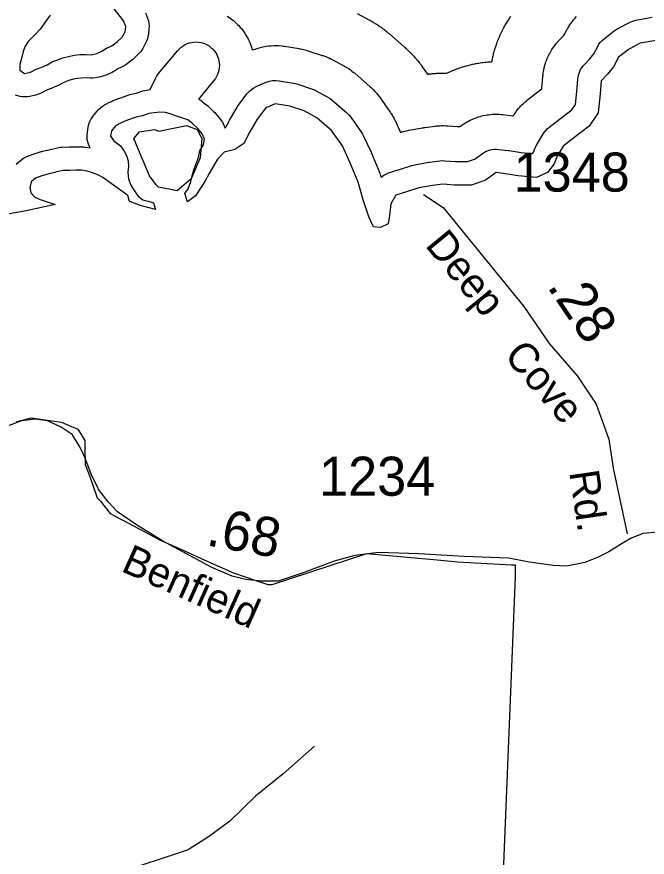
# Model space of a CAD drawing. Extents: x 1113032 to 1302912, y 664689 to 832535.
# Drawn here: x 1144794 to 1146811, y 736082 to 738772 of the extents above; entities that cross this region are included whole.
import ezdxf

# ---------------------------------------------------------------- set-up
doc = ezdxf.new("R2010")
doc.units = 0
for name, color, linetype in [('Exist Boundary Land Use Park State Division NC Parks and Recreation', 7, 'Continuous'), ('Exist Hydrographic Buffer Line', 7, 'Continuous'), ('Exist Hydrographic Island Shore', 7, 'Continuous'), ('Exist Hydrographic Lake Shore', 7, 'Continuous'), ('Exist Hydrographic Misc Water Feature', 7, 'Continuous'), ('Exist Road Non-System Type 51', 7, 'Continuous'), ('Exist Road Non-System Type 51 Label', 7, 'Continuous'), ('Exist Road Secondary Mileage Hundredths English Label', 7, 'Continuous'), ('Exist Road Secondary Type 51 Attributed', 7, 'Continuous'), ('Exist Road Secondary Type 51 Label', 7, 'Continuous'), ('Exist Road Secondary Type 51 Number Label', 7, 'Continuous')]:
    doc.layers.add(name, color=color, linetype=linetype)

msp = doc.modelspace()

# ---------------------------------------------------------------- linework, layer by layer
at = {"layer": 'Exist Boundary Land Use Park State Division NC Parks and Recreation'}
msp.add_lwpolyline([(1144791.7, 737475.3), (1144840.3, 737487.9), (1144869.2, 737483.6), (1144936.9, 737474.7), (1144954.2, 737467.5), (1144988.8, 737451.7), (1145011.3, 737415.5), (1145011.3, 737391.4), (1145012.9, 737338.9), (1145024, 737309.1), (1145038.6, 737269.2), (1145051.2, 737232.5), (1145060.1, 737222.6), (1145092.1, 737182.2), (1145108.3, 737173.3), (1145203.3, 737124), (1145249.9, 737098.3), (1145318.6, 737067.9), (1145395.6, 737032.5), (1145487.2, 736992.7), (1145562.1, 736966.9), (1145597.3, 736955.2), (1145611.3, 736955.2), (1145913.9, 737053.7), (1146150.7, 737032.5), (1146205, 737028), (1146279.5, 737023.3), (1146376.5, 737018.2), (1146388.2, 737017.7), (1146388.6, 736979.2), (1146300.2, 734800.2)], dxfattribs=at)
at = {"layer": 'Exist Hydrographic Buffer Line'}
for points in [[(1145206, 738784.8), (1145212.5, 738767.4), (1145215, 738759.1), (1145216.6, 738750.5), (1145217.2, 738741.8), (1145216.7, 738733.2), (1145214.8, 738715.2), (1145213.6, 738707.9), (1145211.8, 738700.9), (1145209.3, 738694), (1145206.1, 738687.4), (1145197, 738670.6), (1145190.5, 738660.7), (1145182.6, 738651.9), (1145168, 738638.2), (1145164.9, 738635.4), (1145161.5, 738632.7), (1145142.5, 738618.4), (1145135.1, 738613.6), (1145127.1, 738609.6), (1145116.7, 738605.1), (1145107, 738598.7), (1145102.9, 738596.3), (1145098.6, 738594), (1145082.3, 738586.2), (1145072.8, 738582.4), (1145062.9, 738579.9), (1145044.5, 738576.7), (1145036.5, 738575.7), (1145028.6, 738575.6), (1145013.2, 738576.1), (1145000.4, 738575.7), (1144988, 738574.3), (1144975.6, 738572), (1144963.4, 738568.7), (1144951.5, 738564.6), (1144940.1, 738559.6), (1144926.1, 738552.2), (1144923.4, 738550.8), (1144920.7, 738549.6), (1144903.6, 738542.2), (1144902.2, 738541.6), (1144900.7, 738541), (1144886.3, 738535.4), (1144871.6, 738527.8), (1144862.8, 738524), (1144853.6, 738521.3), (1144835.3, 738517.2), (1144827.7, 738515.9), (1144819.9, 738515.4), (1144812.1, 738515.7), (1144804.4, 738516.8), (1144796.8, 738518.7), (1144789.5, 738521.4)], [(1144791.5, 738300.3), (1144805.4, 738312), (1144815.3, 738319.1), (1144826.2, 738324.5), (1144846.1, 738332.4), (1144849.1, 738333.5), (1144852.2, 738334.5), (1144871.7, 738340.4), (1144874, 738341), (1144876.4, 738341.6), (1144906, 738348.5), (1144906.2, 738348.5), (1144906.3, 738348.5), (1144925, 738352.8), (1144932.1, 738354), (1144939.2, 738354.6), (1144960.9, 738355.3), (1144979.5, 738356), (1144982.4, 738356.1), (1144985.3, 738356.1), (1145003.5, 738355.4), (1145007.9, 738355.1), (1145012.2, 738354.6), (1145028.8, 738352), (1145026.1, 738357), (1145023.2, 738364), (1145021, 738371.3), (1145019.5, 738378.7), (1145018.8, 738386.2), (1145018.9, 738393.8), (1145019.7, 738401.3), (1145022.6, 738419), (1145024.7, 738428.2), (1145027.9, 738436.9), (1145032.1, 738445.3), (1145037.4, 738453), (1145049.9, 738469.1), (1145055.2, 738475.3), (1145061.2, 738480.8), (1145067.7, 738485.7), (1145074.7, 738489.8), (1145093, 738499.3), (1145096.3, 738500.9), (1145099.7, 738502.3), (1145117.3, 738509.3), (1145118.5, 738509.8), (1145119.8, 738510.3), (1145150, 738521.1), (1145155.1, 738522.7), (1145160.2, 738523.9), (1145175.8, 738527.1), (1145190.8, 738532.5), (1145197, 738534.4), (1145203.4, 738535.8), (1145220.1, 738538.6), (1145237.5, 738574.5), (1145242, 738582.4), (1145247.3, 738589.8), (1145309.4, 738664.3), (1145314.4, 738669.7), (1145319.8, 738674.6), (1145325.8, 738678.9), (1145332.1, 738682.7), (1145338.8, 738685.8), (1145345.8, 738688.2), (1145352.9, 738689.9), (1145360.2, 738691), (1145367.5, 738691.3), (1145374.9, 738690.8), (1145382.2, 738689.7), (1145389.3, 738687.9), (1145396.2, 738685.3), (1145402.8, 738682.2), (1145409.1, 738678.3), (1145415, 738673.9), (1145420.4, 738668.9), (1145425.3, 738663.4), (1145429.7, 738657.5), (1145433.4, 738651.1), (1145436.5, 738644.5), (1145438.9, 738637.5), (1145440.7, 738630.4), (1145441.7, 738623.1), (1145442, 738615.7), (1145441.6, 738608.4), (1145440.5, 738601.1), (1145438.6, 738594), (1145436.1, 738587.1), (1145432.9, 738580.4), (1145429.1, 738574.1), (1145424.6, 738568.3), (1145374.9, 738508.6), (1145378.7, 738506.6), (1145384.3, 738503.1), (1145389.6, 738499), (1145404.7, 738486.4), (1145406, 738485.3), (1145407.2, 738484.2), (1145423.6, 738469.2), (1145427.8, 738465), (1145431.7, 738460.5), (1145445.3, 738443.4), (1145450.5, 738435.9), (1145454.8, 738427.7), (1145459.8, 738416.6), (1145460.1, 738416.7), (1145463.1, 738418.6), (1145473.1, 738437.9), (1145473.8, 738439.2), (1145474.5, 738440.5), (1145497.6, 738480.9), (1145500.1, 738485), (1145502.9, 738488.9), (1145530.4, 738525.3), (1145536.9, 738532.8), (1145544.3, 738539.3), (1145552.5, 738544.9), (1145561.4, 738549.3), (1145592.1, 738562.1), (1145602, 738565.4), (1145612.2, 738567.4), (1145622.6, 738567.9), (1145633, 738566.9), (1145679.1, 738559.4), (1145684.7, 738558.3), (1145690.2, 738556.8), (1145736.8, 738541.7), (1145743.2, 738539.3), (1145749.4, 738536.3), (1145789.3, 738514.8), (1145796.3, 738510.5), (1145802.8, 738505.4), (1145850.2, 738464.3), (1145856.7, 738458), (1145862.3, 738450.9), (1145897, 738401.6), (1145900.5, 738396.1), (1145903.6, 738390.2), (1145927.8, 738338.4), (1145928.6, 738336.7), (1145929.3, 738335), (1145955.3, 738271.2), (1145956.8, 738267.4), (1145958, 738263.6), (1145959.3, 738258.8), (1145959.5, 738259), (1145964.9, 738263), (1145970.8, 738266.5), (1145976.9, 738269.5), (1145983.2, 738271.9), (1146017.5, 738283.2), (1146017.9, 738283.3), (1146018.3, 738283.4), (1146057.7, 738296), (1146062.5, 738297.3), (1146067.4, 738298.3), (1146111.3, 738306), (1146112.9, 738306.3), (1146114.4, 738306.5), (1146147.6, 738310.9), (1146155.8, 738311.5), (1146163.9, 738311.3), (1146197.7, 738308.4), (1146236.1, 738308.3), (1146258.5, 738316.5), (1146284.2, 738334.5), (1146290, 738338.1), (1146296.1, 738341.3), (1146302.4, 738343.8), (1146309, 738345.8), (1146315.7, 738347.2), (1146322.5, 738347.9), (1146329.3, 738348), (1146336.2, 738347.5), (1146366.6, 738343.9), (1146368, 738343.7), (1146369.3, 738343.5), (1146407.2, 738337.6), (1146438.8, 738334.6), (1146439.2, 738334.6), (1146439.5, 738334.5), (1146444.1, 738334.1), (1146444.4, 738334.2), (1146447.3, 738338), (1146452.7, 738352.1), (1146455.4, 738358.4), (1146458.7, 738364.4), (1146478.2, 738396.7), (1146482.1, 738402.4), (1146486.5, 738407.8), (1146491.3, 738412.7), (1146496.6, 738417.2), (1146535.1, 738446.9), (1146570.1, 738474), (1146581.4, 738490.8), (1146585.8, 738532.3), (1146588.9, 738572.2), (1146589.7, 738578.6), (1146591, 738584.8), (1146592.8, 738591), (1146595.2, 738597), (1146598, 738602.7), (1146601.4, 738608.2), (1146605.2, 738613.3), (1146609.4, 738618.2), (1146627.6, 738637.3), (1146640.3, 738653.1), (1146652.5, 738676.7), (1146656.6, 738683.7), (1146661.4, 738690.3), (1146666.9, 738696.2), (1146673.1, 738701.6), (1146705.6, 738726.8), (1146711.2, 738730.8), (1146717.1, 738734.2), (1146754.1, 738753.4), (1146764.3, 738757.8), (1146775.1, 738760.6), (1146826.9, 738770.1)], [(1145467.4, 738774), (1145472, 738771), (1145476.5, 738767.8), (1145482.4, 738763.4), (1145486.7, 738760), (1145490.8, 738756.3), (1145496.2, 738751.4), (1145500.2, 738747.5), (1145503.9, 738743.5), (1145508.8, 738738), (1145512.4, 738733.9), (1145515.8, 738729.5), (1145520.1, 738723.6), (1145523.2, 738719), (1145526.1, 738714.4), (1145529.9, 738708), (1145532.6, 738703.2), (1145535, 738698.3), (1145538.1, 738691.6), (1145540.3, 738686.6), (1145542.2, 738681.4), (1145544.7, 738674.5), (1145546.3, 738669.3), (1145547.5, 738664.9), (1145549, 738665.5), (1145552.7, 738666.9), (1145556.3, 738668.2), (1145566.2, 738671.6), (1145573.6, 738673.8), (1145581.2, 738675.5), (1145591.5, 738677.4), (1145599.1, 738678.6), (1145606.9, 738679.2), (1145617.3, 738679.7), (1145625.1, 738679.8), (1145632.8, 738679.4), (1145643.2, 738678.4), (1145647.1, 738678), (1145650.9, 738677.5), (1145697, 738670), (1145699.1, 738669.6), (1145701.2, 738669.2), (1145706.8, 738668.1), (1145710.9, 738667.2), (1145715.1, 738666.1), (1145720.5, 738664.6), (1145722.6, 738664), (1145724.6, 738663.3), (1145771.2, 738648.3), (1145773.7, 738647.4), (1145776.1, 738646.6), (1145782.5, 738644.2), (1145787.2, 738642.3), (1145791.9, 738640.2), (1145798, 738637.2), (1145800.3, 738636.1), (1145802.6, 738634.9), (1145842.5, 738613.3), (1145845.2, 738611.8), (1145847.8, 738610.3), (1145854.8, 738606), (1145860, 738602.6), (1145864.9, 738599), (1145871.5, 738593.9), (1145873.9, 738592), (1145876.2, 738590), (1145923.6, 738548.9), (1145926.1, 738546.6), (1145928.6, 738544.3), (1145935.1, 738537.9), (1145939.8, 738533), (1145944.2, 738527.9), (1145949.8, 738520.8), (1145951.9, 738518.1), (1145953.9, 738515.3), (1145988.6, 738466.1), (1145990, 738464.1), (1145991.3, 738462), (1145994.9, 738456.5), (1145997.4, 738452.2), (1145999.8, 738447.9), (1146002.9, 738442.1), (1146004, 738439.9), (1146005.1, 738437.6), (1146021.7, 738402), (1146023.9, 738402.7), (1146025.7, 738403.3), (1146027.5, 738403.8), (1146032.3, 738405.1), (1146035.9, 738406.1), (1146039.5, 738406.9), (1146044.4, 738407.9), (1146046.3, 738408.3), (1146048.1, 738408.7), (1146092, 738416.3), (1146092.6, 738416.4), (1146093.1, 738416.5), (1146094.7, 738416.8), (1146095.8, 738417), (1146097, 738417.1), (1146098.5, 738417.4), (1146099.1, 738417.4), (1146099.7, 738417.5), (1146132.9, 738421.9), (1146135.9, 738422.3), (1146138.9, 738422.6), (1146147.1, 738423.2), (1146153.2, 738423.5), (1146159.3, 738423.5), (1146167.4, 738423.2), (1146170.5, 738423.1), (1146173.5, 738422.9), (1146202.7, 738420.4), (1146211.6, 738420.3), (1146220, 738426.2), (1146222.1, 738427.7), (1146224.2, 738429), (1146230, 738432.7), (1146234.4, 738435.4), (1146238.9, 738437.8), (1146245, 738440.9), (1146249.5, 738443.1), (1146254.2, 738445.2), (1146260.6, 738447.7), (1146265.4, 738449.5), (1146270.2, 738451.1), (1146276.8, 738453.1), (1146281.7, 738454.4), (1146286.7, 738455.6), (1146293.4, 738456.9), (1146298.4, 738457.8), (1146303.5, 738458.5), (1146310.3, 738459.2), (1146315.4, 738459.7), (1146320.5, 738459.9), (1146327.3, 738460), (1146332.4, 738460), (1146337.6, 738459.7), (1146344.4, 738459.2), (1146346.9, 738459), (1146349.5, 738458.7), (1146379.9, 738455.1), (1146380.4, 738455), (1146380.9, 738455), (1146382.3, 738454.8), (1146382.5, 738454.8), (1146383.8, 738456.9), (1146385.2, 738459.1), (1146389.1, 738464.9), (1146392.1, 738469.1), (1146395.3, 738473.2), (1146399.6, 738478.5), (1146403, 738482.5), (1146406.5, 738486.3), (1146411.4, 738491.2), (1146415.1, 738494.8), (1146419, 738498.2), (1146424.3, 738502.7), (1146426.3, 738504.4), (1146428.3, 738506), (1146466.7, 738535.5), (1146474.1, 738541.3), (1146474.2, 738542.6), (1146477.2, 738580.9), (1146477.4, 738583.3), (1146477.7, 738585.6), (1146478.5, 738592), (1146479.1, 738596.8), (1146480, 738601.5), (1146481.3, 738607.7), (1146482.4, 738612.4), (1146483.7, 738617), (1146485.5, 738623.2), (1146487, 738627.7), (1146488.7, 738632.2), (1146491, 738638.2), (1146492.9, 738642.6), (1146494.9, 738646.9), (1146497.8, 738652.7), (1146500, 738656.9), (1146502.4, 738661.1), (1146505.8, 738666.6), (1146508.4, 738670.6), (1146511.1, 738674.5), (1146514.9, 738679.7), (1146517.9, 738683.5), (1146520.9, 738687.2), (1146525.2, 738692), (1146526.8, 738693.8), (1146528.4, 738695.5), (1146543.2, 738711), (1146545.8, 738714.3), (1146552.9, 738728), (1146554.3, 738730.7), (1146555.8, 738733.3), (1146559.9, 738740.4), (1146563.1, 738745.5), (1146566.6, 738750.5), (1146571.5, 738757), (1146575.2, 738761.8), (1146579.2, 738766.4), (1146584.8, 738772.3)], [(1145882.4, 738782.7), (1145922.3, 738761.2), (1145923.3, 738760.6), (1145924.3, 738760.1), (1145927, 738758.6), (1145929, 738757.4), (1145931, 738756.3), (1145933.6, 738754.7), (1145934.6, 738754.1), (1145935.6, 738753.5), (1145942.6, 738749.2), (1145944.6, 738748), (1145946.5, 738746.7), (1145951.7, 738743.4), (1145955.5, 738740.8), (1145959.3, 738738.1), (1145964.2, 738734.5), (1145966.1, 738733.1), (1145967.9, 738731.7), (1145974.4, 738726.6), (1145975.4, 738725.9), (1145976.3, 738725.2), (1145978.7, 738723.3), (1145980.5, 738721.8), (1145982.2, 738720.4), (1145984.6, 738718.4), (1145985.5, 738717.6), (1145986.3, 738716.9), (1146033.7, 738675.8), (1146034.7, 738674.9), (1146035.6, 738674.1), (1146038.1, 738671.8), (1146040, 738670.1), (1146041.9, 738668.4), (1146044.3, 738666), (1146045.3, 738665.2), (1146046.2, 738664.3), (1146052.7, 738657.9), (1146054.5, 738656.1), (1146056.2, 738654.3), (1146060.9, 738649.4), (1146064.4, 738645.7), (1146067.8, 738641.8), (1146072.2, 738636.7), (1146073.8, 738634.7), (1146075.4, 738632.7), (1146081.1, 738625.6), (1146081.9, 738624.6), (1146082.6, 738623.6), (1146084.7, 738621), (1146086.3, 738618.9), (1146087.8, 738616.9), (1146089.8, 738614.1), (1146090.5, 738613.1), (1146091.3, 738612.1), (1146108.1, 738588.1), (1146110.8, 738588.5), (1146111.9, 738588.6), (1146113, 738588.8), (1146116.1, 738589.1), (1146118.4, 738589.4), (1146120.6, 738589.6), (1146123.7, 738589.9), (1146124.8, 738590), (1146125.9, 738590.1), (1146134.1, 738590.7), (1146136.4, 738590.9), (1146138.6, 738591), (1146144.7, 738591.3), (1146149.3, 738591.5), (1146153.9, 738591.5), (1146160, 738591.5), (1146162.3, 738591.5), (1146164.6, 738591.4), (1146169.9, 738591.2), (1146169.9, 738591.2), (1146171.7, 738592.1), (1146176.3, 738594.3), (1146179.7, 738595.9), (1146183.2, 738597.5), (1146187.9, 738599.5), (1146189.7, 738600.3), (1146191.5, 738601), (1146197.8, 738603.5), (1146199.6, 738604.3), (1146201.4, 738604.9), (1146206.2, 738606.7), (1146209.8, 738608), (1146213.4, 738609.3), (1146218.3, 738610.9), (1146220.1, 738611.4), (1146221.9, 738612), (1146228.5, 738614), (1146230.3, 738614.5), (1146232.2, 738615), (1146237.1, 738616.4), (1146240.8, 738617.4), (1146244.5, 738618.3), (1146249.5, 738619.4), (1146251.4, 738619.8), (1146253.2, 738620.2), (1146260, 738621.6), (1146261.8, 738621.9), (1146263.7, 738622.3), (1146268.7, 738623.2), (1146272.5, 738623.8), (1146276.3, 738624.4), (1146281.4, 738625), (1146283.3, 738625.3), (1146285.2, 738625.5), (1146292, 738626.2), (1146293.9, 738626.4), (1146295.8, 738626.6), (1146300.9, 738627.1), (1146304.7, 738627.3), (1146308.5, 738627.5), (1146311.9, 738627.7), (1146314.4, 738629.8), (1146314.9, 738632.3), (1146315.2, 738634.1), (1146315.6, 738635.8), (1146316.9, 738642.1), (1146317.3, 738643.9), (1146317.7, 738645.6), (1146318.7, 738650.3), (1146319.6, 738653.8), (1146320.5, 738657.2), (1146321.8, 738661.9), (1146322.3, 738663.6), (1146322.8, 738665.3), (1146324.6, 738671.5), (1146325.1, 738673.2), (1146325.7, 738674.9), (1146327.2, 738679.5), (1146328.3, 738682.9), (1146329.5, 738686.2), (1146331.2, 738690.7), (1146331.8, 738692.4), (1146332.5, 738694.1), (1146334.8, 738700.1), (1146335.5, 738701.7), (1146336.2, 738703.4), (1146338.1, 738707.8), (1146339.5, 738711.1), (1146341, 738714.4), (1146343, 738718.7), (1146343.8, 738720.3), (1146344.6, 738721.9), (1146347.5, 738727.7), (1146348.3, 738729.3), (1146349.1, 738730.9), (1146351.3, 738735.1), (1146353, 738738.3), (1146354.8, 738741.4), (1146357.2, 738745.5), (1146358.1, 738747.1), (1146359.1, 738748.6), (1146362.4, 738754.1), (1146363.4, 738755.6), (1146364.3, 738757.2), (1146366.9, 738761.2), (1146368.9, 738764.2), (1146370.9, 738767.2), (1146373.7, 738771.1), (1146374.7, 738772.6)]]:
    msp.add_lwpolyline(points, dxfattribs=at)
at = {"layer": 'Exist Hydrographic Island Shore'}
msp.add_lwpolyline([(1144900.2, 738776.8), (1144890.3, 738761.5), (1144879.5, 738746.7), (1144868.1, 738732.4), (1144856.1, 738718.7), (1144843.5, 738705.6), (1144830.3, 738693.1), (1144820.9, 738677.6), (1144814.7, 738660.2), (1144809.8, 738642.2), (1144804, 738619.3), (1144803.5, 738601.1), (1144818.9, 738590.4), (1144837.2, 738594.5), (1144855.5, 738604), (1144873.8, 738611), (1144890.9, 738618.4), (1144907.4, 738627.2), (1144924.1, 738634.5), (1144941.4, 738640.5), (1144959, 738645.2), (1144976.9, 738648.6), (1144995, 738650.6), (1145013.3, 738651.2), (1145031.3, 738650.5), (1145049.8, 738653.8), (1145066.1, 738661.6), (1145081.2, 738671.4), (1145097.5, 738678.4), (1145116.5, 738692.7), (1145131.1, 738706.5), (1145140.2, 738723.3), (1145142.2, 738741.2), (1145135.7, 738758.6), (1145046.1, 738876.4)], dxfattribs=at)
at = {"layer": 'Exist Hydrographic Lake Shore'}
for points in [[(1146845, 738697.2), (1146788.6, 738686.9), (1146751.6, 738667.6), (1146719.1, 738642.4), (1146703.5, 738612.1), (1146684.2, 738587.9), (1146663.7, 738566.4), (1146660.5, 738525.5), (1146654, 738464.5), (1146625.7, 738422.1), (1146580.9, 738387.5), (1146542.4, 738357.8), (1146522.8, 738325.5), (1146513.5, 738300.9), (1146492.2, 738273.4), (1146456.3, 738257.4), (1146431.8, 738259.9), (1146397.9, 738263.1), (1146357.7, 738269.4), (1146327.3, 738273.1), (1146293.5, 738249.4), (1146249.2, 738233.2), (1146194.4, 738233.4), (1146157.5, 738236.6), (1146124.3, 738232.2), (1146080.4, 738224.5), (1146040.9, 738212), (1146006.7, 738200.7), (1145990.5, 738172.9), (1145986.2, 738135.9), (1145982.2, 738109.1), (1145957.8, 738097.6), (1145935.7, 738100), (1145920.1, 738131.9), (1145902.3, 738185.8), (1145885.9, 738242.9), (1145859.9, 738306.7), (1145835.7, 738358.5), (1145801, 738407.7), (1145753.6, 738448.8), (1145713.8, 738470.3), (1145667.1, 738485.4), (1145621, 738492.9), (1145590.2, 738480.1), (1145562.7, 738443.7), (1145539.7, 738403.3), (1145520.4, 738366.3), (1145491, 738347.4), (1145457.8, 738338.3), (1145436.1, 738315.9), (1145409.5, 738270.4), (1145395.6, 738245.1), (1145365.9, 738198.5), (1145339.6, 738180.1), (1145332, 738206.1), (1145342.3, 738221.2), (1145350.4, 738244.2), (1145354.5, 738263.1), (1145361, 738285.6), (1145368, 738302.1), (1145375, 738321), (1145379.5, 738342.7), (1145390.8, 738362.5), (1145394.1, 738380), (1145386.5, 738396.8), (1145373, 738413.9), (1145356.6, 738428.9), (1145341.5, 738441.5), (1145322.1, 738448.4), (1145304.7, 738453.5), (1145287.9, 738460.6), (1145270.1, 738465), (1145252, 738466.4), (1145233.8, 738464.8), (1145215.9, 738461.8), (1145196, 738454.7), (1145175.3, 738450.5), (1145145, 738439.7), (1145127.4, 738432.6), (1145109.2, 738423.2), (1145096.6, 738407.1), (1145093.8, 738389.3), (1145104.5, 738375.1), (1145125.5, 738358.5), (1145136.8, 738344.3), (1145145.1, 738328.1), (1145150.2, 738310.6), (1145151.6, 738292.4), (1145149.3, 738274.4), (1145151.7, 738252.4), (1145158.4, 738232.5), (1145169, 738215.4), (1145182.4, 738198), (1145196.6, 738186.5), (1145213.7, 738181.6), (1145231.4, 738176.6), (1145237.5, 738155.3), (1145193.2, 738167.2), (1145154.6, 738181.1)], [(1145154.6, 738181.1), (1145148.7, 738199.5), (1145069.2, 738257.1), (1145053.3, 738265.9), (1145036.4, 738272.8), (1145018.7, 738277.7), (1145000.8, 738280.4), (1144982.5, 738281.1), (1144963.7, 738280.3), (1144941.6, 738279.6), (1144922.9, 738275.4), (1144893.2, 738268.5), (1144873.8, 738262.7), (1144853.9, 738254.8), (1144840, 738243.1), (1144835, 738225.7), (1144838.8, 738208.1), (1144851.4, 738194.7), (1144869.1, 738187.4), (1144916.6, 738170.8), (1144823.8, 738150.7), (1144747.1, 738136.5)]]:
    msp.add_lwpolyline(points, dxfattribs=at)
at = {"layer": 'Exist Hydrographic Misc Water Feature'}
for points in [[(1145239.5, 738234.3), (1145218.3, 738263), (1145186.5, 738338), (1145167.8, 738382.6), (1145186.5, 738404), (1145234.8, 738410.6), (1145248.6, 738406.2)], [(1145248.6, 738406.2), (1145337.3, 738423.6), (1145370.8, 738410.6), (1145386, 738382.1), (1145380.1, 738320.3)], [(1145380.1, 738320.3), (1145352.1, 738253), (1145306.9, 738214.3), (1145247.3, 738226), (1145239.5, 738234.3)], [(1145746.8, 736438.1), (1145646.1, 736349), (1145557.9, 736277.6), (1145475.5, 736197.9), (1145410, 736149.8), (1145342.6, 736105.8), (1145110.3, 736028.6)]]:
    msp.add_lwpolyline(points, dxfattribs=at)
at = {"layer": 'Exist Road Non-System Type 51'}
msp.add_lwpolyline([(1146094.9, 738202.7), (1146157.8, 738161.1), (1146416.6, 737845.1), (1146497.3, 737726.6), (1146588.1, 737622.1), (1146647.4, 737532.4), (1146688.3, 737419.9), (1146701.9, 737327.3), (1146747.3, 737117.3)], dxfattribs=at)
at = {"layer": 'Exist Road Secondary Type 51 Attributed'}
msp.add_lwpolyline([(1146844.6, 737122.7), (1146797.6, 737118.1), (1146759.7, 737103.3), (1146731.1, 737086.7), (1146687.8, 737060), (1146654.6, 737042.4), (1146611.2, 737025.8), (1146553.1, 737013.9), (1146509.8, 737015.7), (1146434.1, 737026.8), (1146367.3, 737039.2), (1146225.2, 737044.8), (1146080.4, 737053.1), (1145951.3, 737057.7), (1145875.2, 737048), (1145809.7, 737029.5), (1145707.3, 736990.8), (1145629.8, 736965.9), (1145575.4, 736965.9), (1145525.2, 736971), (1145482.7, 736982), (1145418.2, 737009.7), (1145258.1, 737095.9), (1145177, 737145.8), (1145116.1, 737187.3), (1145085.7, 737219.5), (1145056.1, 737258.3), (1145033.1, 737306.2), (1145010.9, 737364.4), (1144994.3, 737397.6), (1144970.8, 737434.9), (1144935.8, 737458.9), (1144892.4, 737478.3), (1144851.8, 737483.8), (1144808.5, 737478.3), (1144764.2, 737461.7)], dxfattribs=at)
msp.add_lwpolyline([(1146844.6, 737122.7), (1146797.6, 737118.1), (1146759.7, 737103.3), (1146731.1, 737086.7), (1146687.8, 737060), (1146654.6, 737042.4), (1146611.2, 737025.8), (1146553.1, 737013.9), (1146509.8, 737015.7), (1146434.1, 737026.8), (1146367.3, 737039.2), (1146225.2, 737044.8), (1146080.4, 737053.1), (1145951.3, 737057.7), (1145875.2, 737048), (1145809.7, 737029.5), (1145707.3, 736990.8), (1145629.8, 736965.9), (1145575.4, 736965.9), (1145525.2, 736971), (1145482.7, 736982), (1145418.2, 737009.7), (1145258.1, 737095.9), (1145177, 737145.8), (1145116.1, 737187.3), (1145085.7, 737219.5), (1145056.1, 737258.3), (1145033.1, 737306.2), (1145010.9, 737364.4), (1144994.3, 737397.6), (1144970.8, 737434.9), (1144935.8, 737458.9), (1144892.4, 737478.3), (1144851.8, 737483.8), (1144808.5, 737478.3), (1144764.2, 737461.7)], dxfattribs=at)

# ---------------------------------------------------------------- texts
at = {"layer": 'Exist Road Non-System Type 51 Label'}
for s, rotation, p in [('Deep', 309.3238, (1146098, 738039.8)), ('Cove', 310.97, (1146349.8, 737685.1)), ('Rd.', 278.3805, (1146561.4, 737314.8))]:
    msp.add_text(s, height=95, rotation=rotation, dxfattribs=at).set_placement(p)
at = {"layer": 'Exist Road Secondary Mileage Hundredths English Label'}
for s, rotation, p in [('.28', 304.0098, (1146488.8, 737908.5)), ('.68', 349.6965, (1145396.9, 737081))]:
    msp.add_text(s, height=125, rotation=rotation, dxfattribs=at).set_placement(p)
at = {"layer": 'Exist Road Secondary Type 51 Label'}
msp.add_text('Benfield', height=95, rotation=335.9038, dxfattribs=at).set_placement((1145123.8, 736999.2))
at = {"layer": 'Exist Road Secondary Type 51 Number Label'}
for s, p in [('1348', (1146383.4, 738212.3)), ('1234', (1145761, 737239))]:
    msp.add_text(s, height=125, dxfattribs=at).set_placement(p)

doc.saveas('drawing.dxf')
